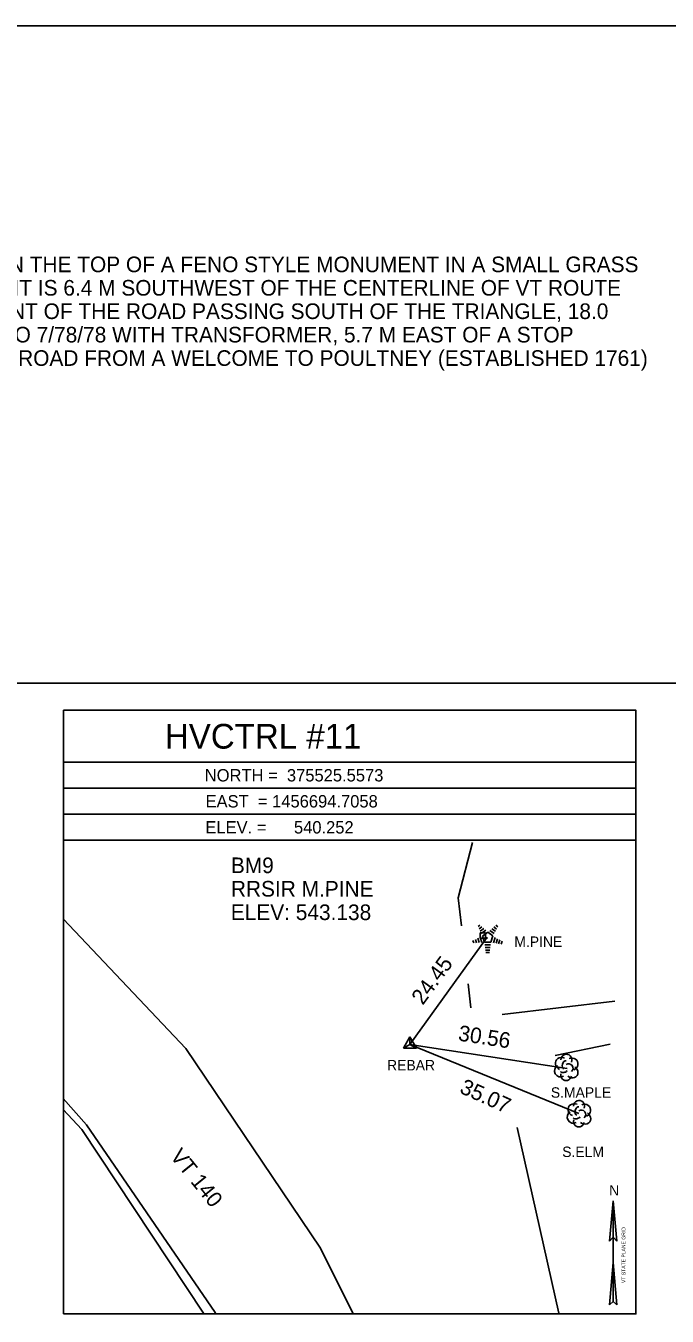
# Model space of a CAD drawing. Extents: x 1454446 to 1455086, y 375501 to 375921.
# Drawn here: x 1454594.1 to 1454717.4, y 375672.7 to 375920.6 of the extents above; entities that cross this region are included whole.
import ezdxf

# ---------------------------------------------------------------- set-up
doc = ezdxf.new("R2010")
doc.units = 0
for name, color, linetype in [('C_A', 7, 'Continuous'), ('CPBM', 7, 'Continuous'), ('CPSM', 7, 'Continuous'), ('Default', 7, 'Continuous'), ('L_C', 7, 'Continuous'), ('LAWA', 7, 'Continuous'), ('LTC', 7, 'Continuous'), ('LTD', 7, 'Continuous'), ('NBL1', 7, 'Continuous'), ('NBL2', 7, 'Continuous'), ('NNA_P', 7, 'Continuous'), ('PET', 7, 'Continuous'), ('RDW', 7, 'Continuous'), ('RGR', 7, 'Continuous')]:
    doc.layers.add(name, color=color, linetype=linetype)

msp = doc.modelspace()

# ---------------------------------------------------------------- linework, layer by layer
at = {"layer": 'CPBM'}
for p, q in [((1454681.45, 375745.31), (1454681.45, 375746.31)), ((1454681.45, 375746.31), (1454682.45, 375746.31)), ((1454682.45, 375745.31), (1454681.45, 375745.31)), ((1454681.96, 375745.81), (1454681.96, 375745.81)), ((1454681.96, 375745.81), (1454681.96, 375745.81)), ((1454682.45, 375746.31), (1454682.45, 375745.31))]:
    msp.add_line(p, q, dxfattribs=at)
at = {"layer": 'CPSM'}
for p, q in [((1454666.69, 375724.17), (1454667.94, 375726.34)), ((1454669.19, 375724.17), (1454667.94, 375726.34)), ((1454667.94, 375724.89), (1454667.94, 375726.34)), ((1454666.69, 375724.17), (1454667.94, 375724.89)), ((1454666.69, 375724.17), (1454669.19, 375724.17)), ((1454667.94, 375724.89), (1454667.94, 375724.89)), ((1454667.94, 375724.89), (1454669.19, 375724.17))]:
    msp.add_line(p, q, dxfattribs=at)
at = {"layer": 'Default'}
for p, q in [((1454682.78, 375745.46), (1454667.94, 375724.89)), ((1454698.14, 375720.23), (1454667.92, 375724.89)), ((1454667.92, 375724.89), (1454700.42, 375711.62))]:
    msp.add_line(p, q, dxfattribs=at)
at = {"layer": 'LAWA'}
for points in [[(1454677.85, 375747.66), (1454677.23, 375753.04), (1454679.94, 375763.69)], [(1454679.65, 375731.9), (1454679.12, 375736.54)], [(1454696.56, 375673.26), (1454688.53, 375708.92)]]:
    msp.add_lwpolyline(points, dxfattribs=at)
at = {"layer": 'LTC'}
for p, q in [((1454681.03, 375747.57), (1454681.38, 375747.82)), ((1454684.43, 375747.81), (1454684.85, 375747.5)), ((1454680.97, 375745.28), (1454681.24, 375744.44)), ((1454681.24, 375747.1), (1454681.77, 375747.48)), ((1454681.43, 375745.49), (1454681.76, 375744.48)), ((1454681.45, 375746.63), (1454682.15, 375747.15)), ((1454681.66, 375746.17), (1454682.54, 375746.81)), ((1454681.88, 375745.71), (1454682.89, 375746.45)), ((1454681.88, 375745.71), (1454682.27, 375744.52)), ((1454682.89, 375746.45), (1454683.89, 375745.72)), ((1454683.31, 375746.76), (1454684.12, 375746.17)), ((1454683.89, 375745.72), (1454683.5, 375744.52)), ((1454683.69, 375747.11), (1454684.37, 375746.62)), ((1454684.33, 375745.45), (1454683.99, 375744.41)), ((1454684.06, 375747.46), (1454684.61, 375747.06)), ((1454684.77, 375745.2), (1454684.49, 375744.32)), ((1454680.06, 375744.85), (1454680.21, 375744.38)), ((1454680.52, 375745.06), (1454680.73, 375744.41)), ((1454683.5, 375744.52), (1454682.27, 375744.52)), ((1454683.46, 375744.02), (1454682.32, 375744.02)), ((1454683.38, 375743.52), (1454682.39, 375743.52)), ((1454683.29, 375743.02), (1454682.46, 375743.02)), ((1454685.22, 375744.95), (1454684.98, 375744.22)), ((1454685.66, 375744.7), (1454685.48, 375744.13)), ((1454683.21, 375742.52), (1454682.54, 375742.52))]:
    msp.add_line(p, q, dxfattribs=at)
at = {"layer": 'LTD'}
for p, q in [((1454697.97, 375720.51), (1454697.97, 375720.51)), ((1454697.97, 375720.51), (1454697.97, 375720.51)), ((1454700.42, 375711.62), (1454700.42, 375711.62)), ((1454700.42, 375711.62), (1454700.42, 375711.62))]:
    msp.add_line(p, q, dxfattribs=at)
for centre in [(1454698.02, 375721.94), (1454700.46, 375713.06)]:
    msp.add_arc(centre, 1.05, 335.5272, 180.9563, dxfattribs=at)
for centre, major_axis, ratio, start_param, end_param in [((1454696.89, 375719.8), (0.58, -1.04), 0.959034, 3.141593, 6.283185), ((1454697.18, 375721.17), (1.21, -0.51), 0.895232, 1.570796, 4.712389), ((1454697.76, 375720.96), (-0.208, -0.792), 0.645439, 3.141593, 6.283185), ((1454698.47, 375720.34), (-0.5, 0.667), 0.989748, 3.141593, 6.283185), ((1454698.97, 375719.67), (-1.09, 0.79), 0.841452, 1.570796, 4.712389), ((1454699.01, 375721.09), (-1.14, -0.48), 0.949671, 1.570796, 4.712389), ((1454697.97, 375719.01), (0.26, 1.06), 0.942809, 1.570796, 4.712389), ((1454697.51, 375719.76), (-0.625, -0.083), 0.423636, 0, 3.141593), ((1454699.63, 375712.29), (1.21, -0.51), 0.895232, 1.570796, 4.712389), ((1454700.21, 375712.08), (-0.208, -0.792), 0.645439, 3.141593, 6.283185), ((1454701.46, 375712.21), (-1.14, -0.48), 0.949671, 1.570796, 4.712389), ((1454699.33, 375710.91), (0.58, -1.04), 0.959034, 3.141593, 6.283185), ((1454699.96, 375710.87), (-0.625, -0.083), 0.423636, 0, 3.141593), ((1454700.92, 375711.46), (-0.5, 0.667), 0.989748, 3.141593, 6.283185), ((1454701.42, 375710.79), (-1.09, 0.79), 0.841452, 1.570796, 4.712389), ((1454700.42, 375710.12), (0.26, 1.06), 0.942809, 1.570796, 4.712389)]:
    msp.add_ellipse(centre, major_axis=major_axis, ratio=ratio, start_param=start_param, end_param=end_param, dxfattribs=at)
at = {"layer": 'NBL1'}
msp.add_lwpolyline([(1454446.38, 375500.6), (1455086.38, 375500.6), (1455086.38, 375920.6), (1454446.38, 375920.6)], close=True, dxfattribs=at)
at = {"layer": 'NBL2'}
for p, q in [((1454446.38, 375794.27), (1455086.38, 375794.27)), ((1454711.37, 375779.1), (1454601.37, 375779.1)), ((1454711.37, 375774.1), (1454601.37, 375774.1)), ((1454711.37, 375769.1), (1454601.37, 375769.1)), ((1454711.37, 375764.1), (1454601.37, 375764.1))]:
    msp.add_line(p, q, dxfattribs=at)
msp.add_lwpolyline([(1454601.37, 375673.1), (1454711.37, 375673.1), (1454711.37, 375789.1), (1454601.37, 375789.1)], close=True, dxfattribs=at)
at = {"layer": 'NNA_P'}
for p, q in [((1454706.32, 375687.06), (1454707.01, 375694.85)), ((1454707.01, 375675.47), (1454707.01, 375694.85)), ((1454707.7, 375687.06), (1454707.01, 375694.85)), ((1454706.32, 375687.06), (1454707.01, 375687.82)), ((1454707.71, 375687.06), (1454707.01, 375687.82)), ((1454707.01, 375683), (1454706.29, 375674.83)), ((1454707.01, 375683), (1454707.73, 375674.83)), ((1454707.01, 375675.47), (1454706.29, 375674.83)), ((1454707.01, 375675.47), (1454707.73, 375674.83))]:
    msp.add_line(p, q, dxfattribs=at)
at = {"layer": 'PET'}
for points in [[(1454656.95, 375673.26), (1454650.78, 375685.76), (1454624.87, 375724.1), (1454601.3, 375749.01)], [(1454630.59, 375673.26), (1454630.53, 375673.38), (1454605.79, 375709.42), (1454601.3, 375714.52)]]:
    msp.add_lwpolyline(points, dxfattribs=at)
at = {"layer": 'RDW'}
for points in [[(1454707.3, 375733.22), (1454685.7, 375730.65)], [(1454695.85, 375722.77), (1454706.43, 375724.92)]]:
    msp.add_lwpolyline(points, dxfattribs=at)
at = {"layer": 'RGR'}
msp.add_lwpolyline([(1454628.27, 375673.26), (1454604.84, 375708.52), (1454601.3, 375712.38)], dxfattribs=at)

# ---------------------------------------------------------------- texts
at = {"layer": 'C_A'}
msp.add_text('REBAR', height=2, dxfattribs=at).set_placement((1454663.55, 375719.89))
at = {"layer": 'Default'}
for s, p in [('THE MARK IS SET 5 CM BELOW GROUND SURFACE IN THE TOP OF A FENO STYLE MONUMENT IN A SMALL GRASS ', (1454488.53, 375873.26)), ('TRIANGLE NORTH OF THE EAST POULTNEY GREEN. IT IS 6.4 M SOUTHWEST OF THE CENTERLINE OF VT ROUTE ', (1454488.53, 375868.76)), ('140, 2.3 M NORTH OF THE NORTH EDGE OF PAVEMENT OF THE ROAD PASSING SOUTH OF THE TRIANGLE, 18.0 ', (1454488.53, 375864.26)), ('M SOUTH OF AND ACROSS THE ROAD FROM POLE NO 7/78/78 WITH TRANSFORMER, 5.7 M EAST OF A STOP ', (1454488.53, 375859.76)), ('SIGN AND 15.0 M SOUTHWEST OF AND ACROSS THE ROAD FROM A WELCOME TO POULTNEY (ESTABLISHED 1761) ', (1454488.53, 375855.26))]:
    msp.add_text(s, height=3, dxfattribs=at).set_placement(p)
for s, rotation, p in [('BM9', 359.9382, (1454633.52, 375757.8)), ('RRSIR M.PINE', 359.9382, (1454633.52, 375753.3)), ('ELEV: 543.138', 359.9382, (1454633.51, 375748.8)), ('24.45', 53.8511, (1454670.42, 375732.3)), ('30.56', 351.1522, (1454677.09, 375725.65)), ('35.07', 335.7821, (1454677.31, 375715.66)), ('VT 140', 308.993, (1454621.71, 375703.35))]:
    msp.add_text(s, height=3, rotation=rotation, dxfattribs=at).set_placement(p)
at = {"layer": 'L_C'}
for s, p in [('M.PINE', (1454688.01, 375743.62)), ('S.MAPLE', (1454695.03, 375714.65)), ('S.ELM', (1454697.22, 375703.25))]:
    msp.add_text(s, height=2, dxfattribs=at).set_placement(p)
at = {"layer": 'LTC'}
msp.add_text('.', height=1.04, rotation=270, dxfattribs=at).set_placement((1454682.78, 375745.46))
at = {"layer": 'NBL2'}
for s, height, p in [('     HVCTRL #11    ', 4.75, (1454612.02, 375781.72)), ('NORTH =  375525.5573', 2.375, (1454628.5, 375775.41)), ('EAST  = 1456694.7058', 2.375, (1454628.65, 375770.41)), ('ELEV. =      540.252', 2.375, (1454628.61, 375765.41))]:
    msp.add_text(s, height=height, dxfattribs=at).set_placement(p)
at = {"layer": 'NNA_P'}
msp.add_text('N', height=1.97, dxfattribs=at).set_placement((1454706.25, 375695.86))
msp.add_text('VT STATE PLANE GRID', height=0.7, rotation=90.0204, dxfattribs=at).set_placement((1454709.36, 375679.04))

doc.saveas('drawing.dxf')
